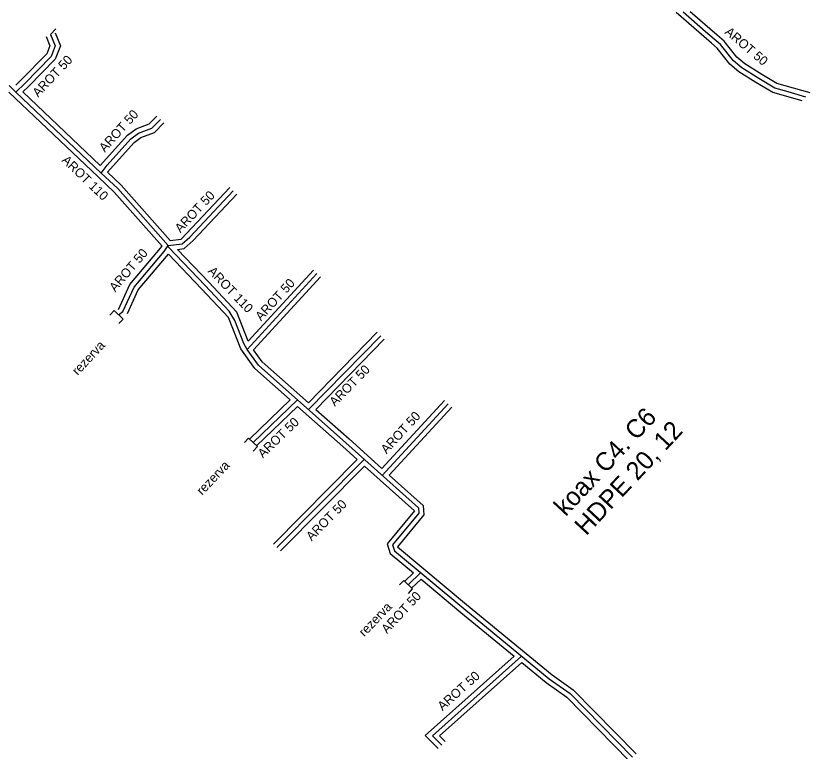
# Model space of a CAD drawing. Extents: x -651943 to -618711, y -1138561 to -1100552.
# Drawn here: x -640828 to -640763.1, y -1114950.9 to -1114890.9 of the extents above; entities that cross this region are included whole.
import ezdxf

# ---------------------------------------------------------------- set-up
doc = ezdxf.new("R2010")
doc.units = 0
for name, color, linetype in [('KT optika', 7, 'Continuous'), ('KT trasa', 7, 'Continuous'), ('KT zařízení', 7, 'Continuous')]:
    doc.layers.add(name, color=color, linetype=linetype)

# ---------------------------------------------------------------- blocks, each defined once
blk = doc.blocks.new('TVREZ')
at = {"layer": 'KT zařízení'}
for p, q in [((-0.05, 0.05), (0, 0.05)), ((0, -0.05), (0, 0.05)), ((-0.05, -0.05), (0, -0.05))]:
    blk.add_line(p, q, dxfattribs=at)

msp = doc.modelspace()

# ---------------------------------------------------------------- linework, layer by layer
at = {"layer": 'KT optika'}
for p, q in [((-640771.67, -1114892.16), (-640773.5, -1114890.57)), ((-640771.67, -1114892.16), (-640773.5, -1114890.57)), ((-640824.727, -1114891.929), (-640825.17, -1114892.4)), ((-640824.727, -1114891.929), (-640825.17, -1114892.4)), ((-640825.17, -1114892.4), (-640824.8, -1114893.32)), ((-640825.17, -1114892.4), (-640824.8, -1114893.32)), ((-640771.32, -1114892.47), (-640771.67, -1114892.16)), ((-640771.32, -1114892.47), (-640771.67, -1114892.16)), ((-640770.44, -1114893.22), (-640771.32, -1114892.47)), ((-640769.4, -1114894.53), (-640770.44, -1114893.22)), ((-640824.8, -1114893.32), (-640825.13, -1114894.18)), ((-640824.8, -1114893.32), (-640825.13, -1114894.18)), ((-640825.13, -1114894.18), (-640827.28, -1114896.38)), ((-640825.13, -1114894.18), (-640827.28, -1114896.38)), ((-640768.71, -1114895.12), (-640769.4, -1114894.53)), ((-640767.32, -1114895.98), (-640768.71, -1114895.12)), ((-640827.28, -1114896.38), (-640828, -1114897.09)), ((-640827.28, -1114896.38), (-640828, -1114897.09)), ((-640766.01, -1114896.77), (-640767.32, -1114895.98)), ((-640828, -1114897.09), (-640828.56, -1114896.56)), ((-640828, -1114897.09), (-640828.56, -1114896.56)), ((-640821.03, -1114903.72), (-640828, -1114897.09)), ((-640821.03, -1114903.72), (-640828, -1114897.09)), ((-640764.92, -1114897.07), (-640766.01, -1114896.77)), ((-640763.492, -1114897.505), (-640764.92, -1114897.07)), ((-640816.204, -1114899.332), (-640816.9, -1114900.04)), ((-640816.204, -1114899.332), (-640816.9, -1114900.04)), ((-640817.98, -1114900.44), (-640816.9, -1114900.04)), ((-640817.98, -1114900.44), (-640816.9, -1114900.04)), ((-640820.55, -1114903.06), (-640818.61, -1114900.91)), ((-640820.55, -1114903.06), (-640818.61, -1114900.91)), ((-640818.61, -1114900.91), (-640817.98, -1114900.44)), ((-640818.61, -1114900.91), (-640817.98, -1114900.44)), ((-640821.03, -1114903.72), (-640820.55, -1114903.06)), ((-640821.03, -1114903.72), (-640820.55, -1114903.06)), ((-640819.68, -1114904.98), (-640821.03, -1114903.72)), ((-640819.68, -1114904.98), (-640821.03, -1114903.72)), ((-640815.56, -1114909.64), (-640819.68, -1114904.98)), ((-640815.56, -1114909.64), (-640819.68, -1114904.98)), ((-640813.8, -1114908.94), (-640810.245, -1114905.165)), ((-640813.8, -1114908.94), (-640810.245, -1114905.165)), ((-640814.42, -1114909.5), (-640813.8, -1114908.94)), ((-640814.42, -1114909.5), (-640813.8, -1114908.94)), ((-640818.35, -1114913.02), (-640815.88, -1114910.12)), ((-640818.35, -1114913.02), (-640815.88, -1114910.12)), ((-640815.88, -1114910.12), (-640815.56, -1114909.64)), ((-640815.88, -1114910.12), (-640815.56, -1114909.64)), ((-640815.56, -1114909.64), (-640814.42, -1114909.5)), ((-640815.56, -1114909.64), (-640814.42, -1114909.5)), ((-640815.54, -1114909.77), (-640815.56, -1114909.64)), ((-640815.54, -1114909.77), (-640815.56, -1114909.64)), ((-640812.55, -1114912.89), (-640815.54, -1114909.77)), ((-640812.55, -1114912.89), (-640815.54, -1114909.77)), ((-640803.412, -1114911.916), (-640809.1, -1114918.13)), ((-640803.412, -1114911.916), (-640809.1, -1114918.13)), ((-640819.26, -1114915.02), (-640818.35, -1114913.02)), ((-640819.26, -1114915.02), (-640818.35, -1114913.02)), ((-640810.59, -1114914.98), (-640812.55, -1114912.89)), ((-640810.59, -1114914.98), (-640812.55, -1114912.89)), ((-640819.61, -1114915.29), (-640819.26, -1114915.02)), ((-640819.61, -1114915.29), (-640819.26, -1114915.02)), ((-640810.12, -1114915.75), (-640810.59, -1114914.98)), ((-640810.12, -1114915.75), (-640810.59, -1114914.98)), ((-640809.38, -1114917.63), (-640810.12, -1114915.75)), ((-640809.38, -1114917.63), (-640810.12, -1114915.75)), ((-640798.204, -1114916.997), (-640804.092, -1114923.038)), ((-640798.204, -1114916.997), (-640804.092, -1114923.038)), ((-640809.1, -1114918.13), (-640809.38, -1114917.63)), ((-640809.1, -1114918.13), (-640809.38, -1114917.63)), ((-640808.19, -1114919.41), (-640809.1, -1114918.13)), ((-640808.19, -1114919.41), (-640809.1, -1114918.13)), ((-640808.19, -1114919.41), (-640801.04, -1114925.74)), ((-640808.19, -1114919.41), (-640801.04, -1114925.74)), ((-640792.703, -1114922.554), (-640798.075, -1114928.405)), ((-640792.703, -1114922.554), (-640798.075, -1114928.405)), ((-640801.04, -1114925.74), (-640795.12, -1114931.06)), ((-640801.04, -1114925.74), (-640795.12, -1114931.06)), ((-640806.676, -1114934.297), (-640799.539, -1114927.089)), ((-640806.676, -1114934.297), (-640799.539, -1114927.089)), ((-640795.1, -1114931.49), (-640797.23, -1114934.09)), ((-640795.1, -1114931.49), (-640797.23, -1114934.09)), ((-640795.12, -1114931.06), (-640795.1, -1114931.49)), ((-640795.12, -1114931.06), (-640795.1, -1114931.49)), ((-640797.08, -1114934.56), (-640791.42, -1114939.27)), ((-640797.08, -1114934.56), (-640791.42, -1114939.27)), ((-640794.93, -1114936.349), (-640795.962, -1114937.341)), ((-640794.93, -1114936.349), (-640795.962, -1114937.341)), ((-640791.42, -1114939.27), (-640784.45, -1114945.02)), ((-640791.42, -1114939.27), (-640784.45, -1114945.02)), ((-640793.984, -1114949.679), (-640786.695, -1114943.168)), ((-640793.984, -1114949.679), (-640786.695, -1114943.168)), ((-640784.45, -1114945.02), (-640782.74, -1114946.23)), ((-640784.45, -1114945.02), (-640782.74, -1114946.23)), ((-640782.74, -1114946.23), (-640777.63, -1114951.43)), ((-640793.224, -1114950.438), (-640793.984, -1114949.679))]:
    msp.add_line(p, q, dxfattribs=at)
at = {"layer": 'KT trasa'}
for p, q in [((-640771.67, -1114892.16), (-640773.5, -1114890.57)), ((-640824.727, -1114891.929), (-640825.17, -1114892.4)), ((-640825.17, -1114892.4), (-640824.8, -1114893.32)), ((-640771.32, -1114892.47), (-640771.67, -1114892.16)), ((-640770.44, -1114893.22), (-640771.32, -1114892.47)), ((-640769.4, -1114894.53), (-640770.44, -1114893.22)), ((-640824.8, -1114893.32), (-640825.13, -1114894.18)), ((-640825.13, -1114894.18), (-640827.28, -1114896.38)), ((-640768.71, -1114895.12), (-640769.4, -1114894.53)), ((-640767.32, -1114895.98), (-640768.71, -1114895.12)), ((-640827.28, -1114896.38), (-640828, -1114897.09)), ((-640766.01, -1114896.77), (-640767.32, -1114895.98)), ((-640828, -1114897.09), (-640828.56, -1114896.56)), ((-640821.03, -1114903.72), (-640828, -1114897.09)), ((-640764.92, -1114897.07), (-640766.01, -1114896.77)), ((-640763.492, -1114897.505), (-640764.92, -1114897.07)), ((-640816.204, -1114899.332), (-640816.9, -1114900.04)), ((-640817.98, -1114900.44), (-640816.9, -1114900.04)), ((-640820.55, -1114903.06), (-640818.61, -1114900.91)), ((-640818.61, -1114900.91), (-640817.98, -1114900.44)), ((-640821.03, -1114903.72), (-640820.55, -1114903.06)), ((-640819.68, -1114904.98), (-640821.03, -1114903.72)), ((-640815.56, -1114909.64), (-640819.68, -1114904.98)), ((-640813.8, -1114908.94), (-640810.245, -1114905.165)), ((-640814.42, -1114909.5), (-640813.8, -1114908.94)), ((-640818.35, -1114913.02), (-640815.88, -1114910.12)), ((-640815.88, -1114910.12), (-640815.56, -1114909.64)), ((-640815.56, -1114909.64), (-640814.42, -1114909.5)), ((-640815.54, -1114909.77), (-640815.56, -1114909.64)), ((-640812.55, -1114912.89), (-640815.54, -1114909.77)), ((-640803.412, -1114911.916), (-640809.1, -1114918.13)), ((-640819.26, -1114915.02), (-640818.35, -1114913.02)), ((-640810.59, -1114914.98), (-640812.55, -1114912.89)), ((-640819.61, -1114915.29), (-640819.26, -1114915.02)), ((-640810.12, -1114915.75), (-640810.59, -1114914.98)), ((-640809.38, -1114917.63), (-640810.12, -1114915.75)), ((-640798.204, -1114916.997), (-640804.092, -1114923.038)), ((-640809.1, -1114918.13), (-640809.38, -1114917.63)), ((-640808.19, -1114919.41), (-640809.1, -1114918.13)), ((-640808.19, -1114919.41), (-640801.04, -1114925.74)), ((-640792.703, -1114922.554), (-640798.075, -1114928.405)), ((-640801.04, -1114925.74), (-640795.12, -1114931.06)), ((-640806.676, -1114934.297), (-640799.539, -1114927.089)), ((-640795.1, -1114931.49), (-640797.23, -1114934.09)), ((-640795.12, -1114931.06), (-640795.1, -1114931.49)), ((-640797.08, -1114934.56), (-640791.42, -1114939.27)), ((-640794.93, -1114936.349), (-640795.962, -1114937.341)), ((-640791.42, -1114939.27), (-640784.45, -1114945.02)), ((-640793.984, -1114949.679), (-640786.695, -1114943.168)), ((-640784.45, -1114945.02), (-640782.74, -1114946.23)), ((-640782.74, -1114946.23), (-640777.63, -1114951.43)), ((-640793.224, -1114950.438), (-640793.984, -1114949.679))]:
    msp.add_line(p, q, dxfattribs=at)
at = {"layer": 'KT zařízení'}
for p, q in [((-640771.196, -1114893.1), (-640774.076, -1114890.598)), ((-640770.721, -1114892.454), (-640772.923, -1114890.541)), ((-640825.541, -1114892.549), (-640825.23, -1114893.323)), ((-640824.798, -1114892.25), (-640824.369, -1114893.316)), ((-640770.151, -1114892.94), (-640770.721, -1114892.454)), ((-640770.729, -1114893.499), (-640771.196, -1114893.1)), ((-640769.11, -1114894.25), (-640770.151, -1114892.94)), ((-640825.23, -1114893.323), (-640825.473, -1114893.959)), ((-640824.369, -1114893.316), (-640824.786, -1114894.4)), ((-640769.689, -1114894.809), (-640770.729, -1114893.499)), ((-640825.473, -1114893.959), (-640827.591, -1114896.125)), ((-640824.786, -1114894.4), (-640826.969, -1114896.634)), ((-640768.474, -1114894.794), (-640769.11, -1114894.25)), ((-640768.945, -1114895.445), (-640769.689, -1114894.809)), ((-640767.082, -1114895.656), (-640768.474, -1114894.794)), ((-640767.557, -1114896.303), (-640768.945, -1114895.445)), ((-640765.85, -1114896.399), (-640767.082, -1114895.656)), ((-640827.591, -1114896.125), (-640828.005, -1114896.534)), ((-640766.169, -1114897.14), (-640767.557, -1114896.303)), ((-640763.131, -1114897.146), (-640765.85, -1114896.399)), ((-640821.294, -1114904.02), (-640828.576, -1114897.092)), ((-640826.969, -1114896.634), (-640827.425, -1114897.084)), ((-640821.113, -1114903.088), (-640827.425, -1114897.084)), ((-640763.784, -1114897.797), (-640766.169, -1114897.14)), ((-640816.489, -1114899.051), (-640817.122, -1114899.695)), ((-640818.172, -1114900.084), (-640817.122, -1114899.695)), ((-640815.918, -1114899.612), (-640816.677, -1114900.384)), ((-640818.877, -1114900.61), (-640818.172, -1114900.084)), ((-640817.787, -1114900.795), (-640816.677, -1114900.384)), ((-640821.113, -1114903.088), (-640818.877, -1114900.61)), ((-640818.342, -1114901.209), (-640817.787, -1114900.795)), ((-640820.532, -1114903.637), (-640818.342, -1114901.209)), ((-640819.394, -1114904.699), (-640820.532, -1114903.637)), ((-640819.965, -1114905.26), (-640821.294, -1114904.02)), ((-640815.4, -1114909.216), (-640819.394, -1114904.699)), ((-640814.507, -1114909.107), (-640810.536, -1114904.89)), ((-640816.044, -1114909.695), (-640819.965, -1114905.26)), ((-640813.516, -1114909.222), (-640809.953, -1114905.439)), ((-640815.4, -1114909.216), (-640814.507, -1114909.107)), ((-640814.246, -1114909.882), (-640813.516, -1114909.222)), ((-640818.691, -1114912.803), (-640816.044, -1114909.695)), ((-640814.812, -1114909.951), (-640814.246, -1114909.882)), ((-640812.252, -1114912.622), (-640814.812, -1114909.951)), ((-640818.008, -1114913.236), (-640815.544, -1114910.342)), ((-640812.847, -1114913.157), (-640815.544, -1114910.342)), ((-640803.707, -1114911.645), (-640809.02, -1114917.449)), ((-640809.957, -1114915.07), (-640812.252, -1114912.622)), ((-640803.116, -1114912.186), (-640808.585, -1114918.161)), ((-640819.624, -1114914.854), (-640818.691, -1114912.803)), ((-640818.895, -1114915.185), (-640818.008, -1114913.236)), ((-640810.647, -1114915.503), (-640812.847, -1114913.157)), ((-640809.02, -1114917.449), (-640809.957, -1114915.07)), ((-640809.64, -1114918.059), (-640810.647, -1114915.503)), ((-640798.49, -1114916.717), (-640804.112, -1114922.485)), ((-640797.917, -1114917.276), (-640803.512, -1114923.016)), ((-640808.489, -1114919.679), (-640809.64, -1114918.059)), ((-640807.89, -1114919.14), (-640808.585, -1114918.161)), ((-640807.89, -1114919.14), (-640804.112, -1114922.485)), ((-640808.489, -1114919.679), (-640805.598, -1114922.239)), ((-640805.598, -1114922.239), (-640808.907, -1114925.421)), ((-640805.008, -1114922.227), (-640808.63, -1114925.71)), ((-640792.997, -1114922.283), (-640798.101, -1114927.842)), ((-640804.996, -1114922.771), (-640808.352, -1114925.998)), ((-640804.996, -1114922.771), (-640801.307, -1114926.037)), ((-640803.512, -1114923.016), (-640800.789, -1114925.427)), ((-640792.408, -1114922.824), (-640797.506, -1114928.377)), ((-640800.789, -1114925.427), (-640798.101, -1114927.842)), ((-640801.307, -1114926.037), (-640800.118, -1114927.105)), ((-640806.96, -1114934.015), (-640800.118, -1114927.105)), ((-640806.391, -1114934.578), (-640799.522, -1114927.641)), ((-640799.522, -1114927.641), (-640795.457, -1114931.294)), ((-640797.506, -1114928.377), (-640794.728, -1114930.874)), ((-640794.728, -1114930.874), (-640794.693, -1114931.624)), ((-640795.457, -1114931.294), (-640797.677, -1114934.004)), ((-640794.693, -1114931.624), (-640796.837, -1114934.241)), ((-640797.677, -1114934.004), (-640797.426, -1114934.791)), ((-640797.23, -1114934.09), (-640797.08, -1114934.56)), ((-640797.426, -1114934.791), (-640795.529, -1114936.37)), ((-640796.837, -1114934.241), (-640791.189, -1114938.942)), ((-640795.529, -1114936.37), (-640796.239, -1114937.052)), ((-640794.91, -1114936.885), (-640795.684, -1114937.629)), ((-640794.91, -1114936.885), (-640791.651, -1114939.597)), ((-640791.189, -1114938.942), (-640784.21, -1114944.699)), ((-640791.651, -1114939.597), (-640787.308, -1114943.179)), ((-640794.566, -1114949.662), (-640787.308, -1114943.179)), ((-640793.401, -1114949.695), (-640786.684, -1114943.694)), ((-640786.684, -1114943.694), (-640784.689, -1114945.34)), ((-640784.21, -1114944.699), (-640782.479, -1114945.923)), ((-640784.689, -1114945.34), (-640783, -1114946.536)), ((-640782.479, -1114945.923), (-640777.348, -1114951.145)), ((-640783, -1114946.536), (-640777.911, -1114951.714)), ((-640793.506, -1114950.721), (-640794.566, -1114949.662)), ((-640792.941, -1114950.154), (-640793.401, -1114949.695))]:
    msp.add_line(p, q, dxfattribs=at)

# ---------------------------------------------------------------- block references
for p, xscale, yscale, rotation in [((-640819.61, -1114915.29), 9.99997728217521, 9.99997728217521, 46.272049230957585), ((-640808.63, -1114925.71), 10.0000070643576, 10.0000070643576, 46.54738294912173), ((-640795.962, -1114937.341), 10.0000070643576, 10.0000070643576, 46.54738294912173)]:
    msp.add_blockref('TVREZ', p, dxfattribs=dict(at, xscale=xscale, yscale=yscale, rotation=rotation))

# ---------------------------------------------------------------- texts
for s, height, rotation, p in [('AROT 50', 0.75, 319.54804, (-640770.16, -1114892.275)), ('AROT 50', 0.75, 46.66379, (-640826.185, -1114897.563)), ('AROT 50', 0.75, 47.93926, (-640820.736, -1114902.06)), ('AROT 110', 0.75, 316.03078, (-640824.307, -1114902.726)), ('AROT 50', 0.75, 46.71914, (-640814.558, -1114908.638)), ('AROT 50', 0.75, 49.57986, (-640819.885, -1114913.465)), ('AROT 110', 0.75, 313.7847, (-640812.373, -1114911.773)), ('AROT 50', 0.75, 47.5317, (-640807.976, -1114915.836)), ('rezerva', 0.75, 46.98936, (-640822.949, -1114920.281)), ('AROT 50', 0.75, 45.54971, (-640801.946, -1114922.814)), ('koax C4. C6', 1.5, 47.02923, (-640783.099, -1114931.821)), ('AROT 50', 0.75, 43.87912, (-640807.821, -1114927.037)), ('AROT 50', 0.75, 47.44338, (-640797.726, -1114926.694)), ('HDPE 20, 12', 1.5, 47.02923, (-640781.414, -1114933.395)), ('rezerva', 0.75, 46.56113, (-640812.785, -1114930.074)), ('AROT 50', 0.75, 45.42474, (-640803.847, -1114933.811)), ('AROT 50', 0.75, 47.0184, (-640797.69, -1114941.381)), ('rezerva', 0.75, 46.56113, (-640799.536, -1114941.631)), ('AROT 50', 0.75, 41.77191, (-640793.152, -1114947.677))]:
    msp.add_text(s, height=height, rotation=rotation, dxfattribs=at).set_placement(p)

doc.saveas('drawing.dxf')
